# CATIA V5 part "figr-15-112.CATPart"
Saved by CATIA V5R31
Part number: Part1
Bounding box of the stored display mesh (mm): x -55.37 to 68.649, y -21.457 to 35.984, z 0 to 57.441
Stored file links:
  D:\PROJECTS\Project 2021\US EDITION\CATIA V5 6R 2021\Resources\Part Files\c15_catia_v5_6r2021_prt\figr-15-112.CATPart
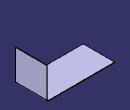
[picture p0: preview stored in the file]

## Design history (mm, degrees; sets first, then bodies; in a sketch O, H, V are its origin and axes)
SheetMetalParameters1: Thickness 1, BendRadius 2, KFactor 0.400515 {= log(min(100,max(20*SheetMetalParameters1.BendRadius,SheetMetalParameters1.Thickness)/SheetMetalParameters1.Thickness))/log(100)/2}, ReliefRadialLength 1, ReliefAxialLength 2, MinimumBendRadius 0
Body1 (main body)
  Sketch1 on xy-plane, origin (0, 0, 0), H (1, 0, 0), V (0, 1, 0)
    line L1 (-55.3695, 35.9836) -> (67.649, 35.9836)
    line L2 (67.649, 35.9836) -> (67.649, -21.4575)
    line L3 (67.649, -21.4575) -> (-55.3695, -21.4575)
    line L4 (-55.3695, -21.4575) -> (-55.3695, 35.9836)
    horizontal: L1 H, L3 H
    vertical: L2 V, L4 V
  Wall1: Thickness 1, Profile Sketch1
  d_NewWallOnEdge1: NewWallOnEdge_Edge edge [face of Wall1 | face of Wall1], NewWallOnEdge_Length 57.4411, NewWallOnEdge_HeightLimitOffset 0, NewWallOnEdge_WidthOffset1 0, NewWallOnEdge_WidthOffset2 0, NewWallOnEdge_Angle 90, NewWallOnEdge_BendRadiusValue 2 {= SheetMetalParameters1.BendRadius}, NewWallOnEdge_BendTable SheetMetalParameters1, KFacteur 0.400515 {= log(min(100,max(20*d_NewWallOnEdge1.Radius,SheetMetalParameters1.Thickness)/SheetMetalParameters1.Thickness))/log(100)/2}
